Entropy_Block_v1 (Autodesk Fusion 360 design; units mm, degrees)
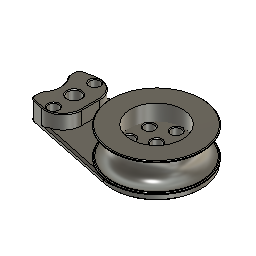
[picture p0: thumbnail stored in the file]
base_mesh_feature "Base Mesh Feature1"
base_mesh_feature "Base Mesh Feature1"
mesh_repair "MeshRepair1"
generate_face_groups "GenerateFaceGroups3" Boundary Tolerance 0.001
convert_mesh "Convert Mesh1" bodies "Body1"
generate_face_groups "GenerateFaceGroups1" Boundary Tolerance 0.001
convert_mesh "Convert Mesh1" bodies "Body1"
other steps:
create_component "CreateComponent1"
create_component "CreateComponent2"
named bodies: "Body1"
